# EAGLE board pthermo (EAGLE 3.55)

Size 80 x 100 mm. Coordinates in mm from the lower left corner, seen from the top.
Outline: 0,0 80,0 80,100 0,100 0,0
Copper layers used: 

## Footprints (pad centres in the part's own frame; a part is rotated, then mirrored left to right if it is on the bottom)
RM2,5 = drill 0.406 pad 1.778 round:  0,0;  2.54,0
KO02 = drill 0.813 pad 2.032 round:  0,0;  5.08,0
KO01 = drill 0.813 pad 1.422 round:  0,0;  2.54,0
O04 = drill 0.406 pad 1.778 round:  0,0;  10.16,0
14 = drill 0.406 pad 1.778 square:  0,0 | drill 0.406 pad 1.778 round:  5.08,0;  10.16,0;  15.24,0;  20.32,0;  22.86,0;  17.78,0;  12.7,0;  7.62,0;  2.54,0;  25.4,0;  27.94,0;  30.48,0;  33.02,0
L-18B = drill 0.61 pad 3.048 offset:  0,0;  2.54,0;  15.24,0;  17.78,0;  5.08,0;  7.62,0;  12.7,0;  10.16,0;  20.32,0;  20.32,7.62;  17.78,7.62;  15.24,7.62;  12.7,7.62;  10.16,7.62;  7.62,7.62;  5.08,7.62;  2.54,7.62;  0,7.62
92 = drill 0.406 pad 1.778 round:  -0.635,0;  1.27,1.905;  3.175,0
GEL = drill 1.295 pad 3.048 round:  0,0
ARZ_ST = drill 0.813 pad 1.422 round:  0,0;  5.08,0
S04 = drill 0.813 pad 1.422 round:  0,0;  10.16,0
S04' = drill 0.406 pad 1.778 round:  0,0;  10.16,0
H-1POL = drill 1.295 pad 2.54 round:  0,0;  5.08,0
HRUNG = drill 3.505 pad 6.452 round:  0,0
92-B = drill 0.813 pad 1.422 round:  -2.54,0;  2.54,0;  0,0

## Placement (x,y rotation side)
C1  27p  [RM2,5]  not placed on the board
C2  100n  [RM2,5]  not placed on the board
C3  27p  [RM2,5]  not placed on the board
C4  100n  [RM2,5]  not placed on the board
C5  100u/25V  [KO02]  not placed on the board
C6  47u  [KO01]  not placed on the board
D1  1N4148  [O04]  not placed on the board
DIS1  LCD  [14]  -35.56,7.62 0 top
IC1  16F84P  [L-18B]  not placed on the board
IC2  DS1821  [92]  not placed on the board
N1  +  [GEL]  not placed on the board
N2  -  [GEL]  not placed on the board
N3  +  [GEL]  not placed on the board
N4  Data  [GEL]  not placed on the board
N5  -  [GEL]  not placed on the board
Q1  4MHz  [ARZ_ST]  not placed on the board
R1  12k  [S04]  not placed on the board
R2  1k  [S04]  not placed on the board
R3  100  [S04]  not placed on the board
R4  10k  [S04]  -12.7,21.59 0 top
R5  10k  [S04']  not placed on the board
R6  4k7  [S04]  not placed on the board
R7  10k  [S04']  not placed on the board
SW1  CLEAR  [H-1POL]  not placed on the board
SW2  MINMAX  [H-1POL]  not placed on the board
U$15  BOHRUNG  [HRUNG]  not placed on the board
U$16  BOHRUNG  [HRUNG]  not placed on the board
U$26  BOHRUNG  [HRUNG]  not placed on the board
U$27  BOHRUNG  [HRUNG]  not placed on the board
VR1  78L05  [92-B]  not placed on the board

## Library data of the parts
C1-C4 D1 DIS1 IC2 R5 R7 = holg_plt
C5 C6 N1-N5 R1-R4 R6 U$15 U$16 U$26 U$27 VR1 = holgnorm
IC1 = PIC
Q1 = bts
SW1 SW2 = taster

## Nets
+5V: C2. C6. DIS1. IC1. R1. R3. R4. R5. R6. R7. VR1.
+UB: C5. D1. VR1.
GND: C1. C2. C3. C4. C5. C6. DIS1. IC1. IC2. N2. N5. R2. SW1. SW2. U$15. U$16. U$26. U$27. VR1.
N$1: C1. IC1. Q1.
N$2: D1. N1.
N$3: C3. IC1. Q1.
N$4: IC2. N3. R3.
N$5: C4. IC1. R4.
N$6: IC1. IC2. N4. R6.
N$9: IC1. R5. SW2.
N$11: DIS1. IC1.
N$12: DIS1. IC1.
N$13: DIS1. IC1.
N$14: DIS1. IC1.
N$15: IC1. R7. SW1.
N$22: DIS1. R1. R2.
N$23: DIS1. IC1.
N$24: DIS1. IC1.

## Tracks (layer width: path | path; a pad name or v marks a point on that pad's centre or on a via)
+5V  (10 unrouted)
+UB  (2 unrouted)
GND  (19 unrouted)
N$1  (2 unrouted)
N$2  (1 unrouted)
N$3  (2 unrouted)
N$4  (2 unrouted)
N$5  (2 unrouted)
N$6  (3 unrouted)
N$9  (2 unrouted)
N$11  (1 unrouted)
N$12  (1 unrouted)
N$13  (1 unrouted)
N$14  (1 unrouted)
N$15  (2 unrouted)
N$22  (2 unrouted)
N$23  (1 unrouted)
N$24  (1 unrouted)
